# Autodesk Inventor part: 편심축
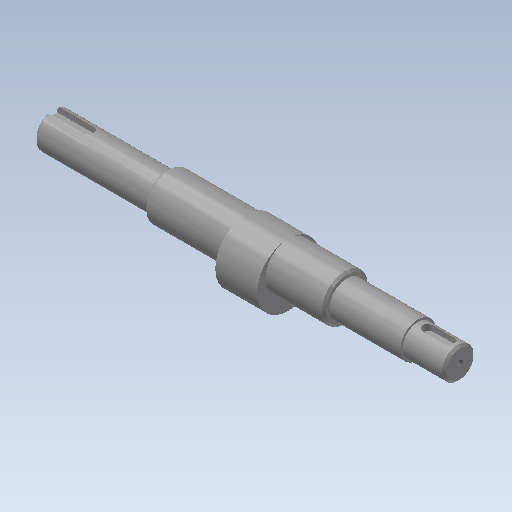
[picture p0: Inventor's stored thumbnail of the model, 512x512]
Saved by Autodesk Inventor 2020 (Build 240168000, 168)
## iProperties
Created: 2016-05
Part Number: 편심축
Document SubType Name: Modeling
Designer: mduedu
Density: 7.86 g/cm^3
Material: 강철, 연강
Appearance: 강철
Author: mduedu
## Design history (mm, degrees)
sketch "스케치1"
  geometry: L1 (-42.5, 11)-(-42.5, 8.5); L2 (43.5, 11)-(43.5, 8.5); L3 (-97.5, 0)-(97.5, 0); L4 (-42.5, 11)-(43.5, 11); L5 (43.5, 11)-(43.5, 8.5); L6 (-42.5, 11)-(-42.5, 8.5); L7 (-42.5, 8.5)-(-97.5, 8.5); L8 (-97.5, 8.5)-(-97.5, 0); L9 (43.5, 8.5)-(77.5, 8.5); L10 (97.5, 7.5)-(97.5, 0); L11 (77.5, 8.5)-(77.5, 7.5); L12 (77.5, 7.5)-(97.5, 7.5); 1 further point
  constraints: 24 end point, 9 perpendicular, 2 midpoint, 1 collinear, 1 horizontal
  dimensions: "d0" = 22 diameter of L4 L3; "d1" = 17 diameter of L7 L3; "d2" = 55 distance between parallel lines of L8 L1; "d3" = 54 distance between parallel lines of L10 L2; "d4" = 15 diameter of L12 L3; "d5" = 20 distance between parallel lines of L10 L11; "d29" = 86 distance of L1.start L2.start
revolve "회전1" stored, may be unused: angle "d6" = 90 deg
node "작업 평면7"
node "작업 평면9"
sketch "스케치2"
  geometry: C1 r 11 at (0, 0); C2 r 15 at (0, -4); C3 r 11 at (0, 0); 2 further points
  constraints: 3 centre point, 2 coincident, 1 concentric, 1 vertical alignment
  dimensions: "d9" = 4 distance of point (0, 0) C2.centre; "d10" = 30 diameter of C2
extrude "돌출1" join sketch "스케치2" stored distance "d11" = 20; taper "d12" = 0 deg
chamfer "모따기1" distance "d17" = 1; stored, may be unused: second distance "d18" = 2, angle "d19" = 45 deg
node "작업 평면4"
sketch "스케치4"
  geometry: L1 (-10, -6.5)-(-10, 6.5) reference; L2 (-5, 2.5)-(5, 2.5); L3 (5, -2.5)-(-5, -2.5); A1 r 2.5 centre (5, 0) between (5, -2.5) and (5, 2.5); A2 r 2.5 centre (-5, 0) between (-5, 2.5) and (-5, -2.5); 2 further points
  constraints: 4 end point, 4 point on circle, 4 tangent, 2 centre point, 1 horizontal alignment, 1 midpoint, 1 parallel, 1 perpendicular
  dimensions: "d20" = 5 distance between parallel lines of L3 L2; "d21" = 15 dimension on A1 A2; "d22" = 2.5 distance edge to line of A2 L1
extrude "돌출3" cut sketch "스케치4" distance "d23" = 3; taper "d24" = 0 deg
node "작업 평면5"
sketch "스케치5"
  geometry: L1 (27.5, 7.5)-(27.5, -7.5) reference; L2 (27.5, 2.5)-(10, 2.5); L3 (10, -2.5)-(27.5, -2.5); A1 r 2.5 centre (10, 0) between (10, 2.5) and (10, -2.5); 2 further points
  constraints: 4 end point, 2 perpendicular, 2 point on circle, 2 point on line, 2 tangent, 1 centre point, 1 horizontal alignment, 1 midpoint
  dimensions: "d25" = 5 distance between parallel lines of L3 L2; "d26" = 20 dimension on A1 L1
extrude "돌출4" cut sketch "스케치5" distance "d27" = 3; taper "d28" = 0 deg
hole "구멍1" diameter "d34" = 3.242; stored, may be unused: countersink angle "d38" = 90 deg, drill point angle "d40" = 118 deg; dims "d35" = 9, "d36" = 4, "d37" = 2, "d39" = 11, "d43" = 10, "d44" = 10
node "솔리드1"
other parameters: "d31" = -38
